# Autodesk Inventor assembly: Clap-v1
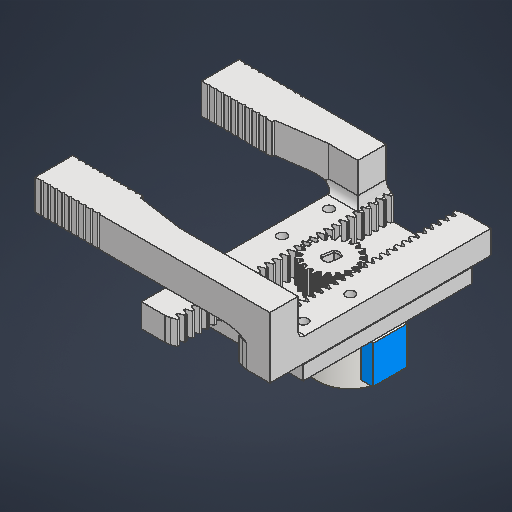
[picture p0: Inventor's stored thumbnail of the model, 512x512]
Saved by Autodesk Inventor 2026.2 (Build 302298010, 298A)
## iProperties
Created: 2026-05
Part Number: Clap-v1
Document SubType Name: Assembly
Designer: work
Author: work
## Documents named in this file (6)
- C:\Users\work\Desktop\ARD_v1\ARD_hardware\RA_Project\clap\Clap-v1.iam
- C:\Users\work\Desktop\ARD_v1\ARD_hardware\RA_Project\clap\moter_holder.ipt
- C:\Users\work\Desktop\ARD_v1\ARD_hardware\RA_Project\clap\Tongs_R.ipt
- C:\Users\work\Desktop\ARD_v1\ARD_hardware\RA_Project\clap\gear_M1.0_Z20_H10.0_O-0.10_spur.ipt
- C:\Users\work\Desktop\ARD_v1\ARD_hardware\RA_Project\28BJY-48.ipt
- C:\Users\work\Desktop\ARD_v1\ARD_hardware\RA_Project\clap\Tongs_L.ipt
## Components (5 placed, 5 different names)
1. moter_holder:1 — 각도:1, 플러쉬:1, 각도:2, 플러쉬:2
2. Tongs_R:1 — 각도:1, 플러쉬:1
3. gear_M1.0_Z20_H10.0_O-0.10_spur:1
4. 28BJY-48:1
5. Tongs_L:1 — 각도:2, 플러쉬:2
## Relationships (4: Angle 2, Flush 2)
- 각도:1 [Angle]: moter_holder:1 ↔ Tongs_R:1
- 플러쉬:1 [Flush]: moter_holder:1 ↔ Tongs_R:1
- 각도:2 [Angle]: moter_holder:1 ↔ Tongs_L:1
- 플러쉬:2 [Flush]: moter_holder:1 ↔ Tongs_L:1
